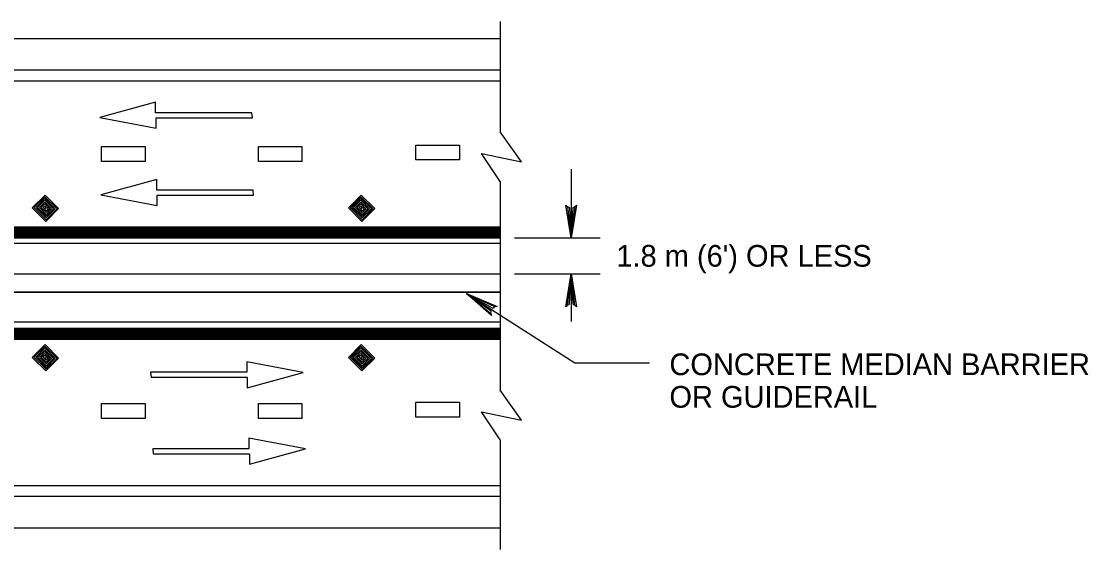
# Model space of a CAD drawing. Extents: x 639362 to 641108, y 298458 to 299646.
# Drawn here: x 639830.9 to 639978.6, y 299371.1 to 299444.2 of the extents above; entities that cross this region are included whole.
import ezdxf

# ---------------------------------------------------------------- set-up
doc = ezdxf.new("R2010")
doc.units = 0
doc.layers.add('2', color=7, linetype='Continuous')

msp = doc.modelspace()

# ---------------------------------------------------------------- linework, layer by layer
at = {"layer": '2'}
for p, q in [((639897.17, 299444.19), (639897.17, 299428.91)), ((639662.67, 299441.83), (639897.17, 299441.83)), ((639662.67, 299437.48), (639897.17, 299437.48)), ((639662.67, 299435.98), (639897.17, 299435.98)), ((639849.5, 299433.01), (639841.78, 299430.89)), ((639849.5, 299431.56), (639849.5, 299433.01)), ((639841.78, 299430.89), (639849.58, 299429.42)), ((639862.83, 299431.56), (639849.5, 299431.56)), ((639849.58, 299429.42), (639849.58, 299430.86)), ((639849.58, 299430.86), (639862.91, 299430.86)), ((639862.91, 299430.89), (639862.83, 299431.56)), ((639862.91, 299430.86), (639862.91, 299430.89)), ((639900.12, 299424.78), (639897.17, 299428.91)), ((639842.04, 299424.83), (639842.04, 299426.9)), ((639842.04, 299426.9), (639848.05, 299426.9)), ((639848.05, 299426.9), (639848.05, 299424.83)), ((639863.74, 299424.83), (639863.74, 299426.9)), ((639863.74, 299426.9), (639869.75, 299426.9)), ((639869.75, 299426.9), (639869.75, 299424.83)), ((639885.51, 299425.02), (639885.51, 299427.08)), ((639885.51, 299427.08), (639891.52, 299427.08)), ((639891.52, 299427.08), (639891.52, 299425.02)), ((639897.17, 299422.04), (639894.6, 299425.91)), ((639894.6, 299425.91), (639900.12, 299424.78)), ((639848.05, 299424.83), (639842.04, 299424.83)), ((639869.75, 299424.83), (639863.74, 299424.83)), ((639891.52, 299425.02), (639885.51, 299425.02)), ((639906.99, 299423.74), (639906.99, 299414.25)), ((639849.65, 299422.3), (639841.93, 299420.18)), ((639849.65, 299420.86), (639849.65, 299422.3)), ((639897.17, 299422.04), (639897.17, 299393.18)), ((639832.45, 299418.4), (639834.21, 299420.17)), ((639832.67, 299418.44), (639834.18, 299419.94)), ((639834.18, 299419.94), (639835.87, 299418.25)), ((639834.21, 299420.17), (639836.09, 299418.29)), ((639841.93, 299420.18), (639849.73, 299418.71)), ((639862.98, 299420.86), (639849.65, 299420.86)), ((639849.73, 299418.71), (639849.73, 299420.15)), ((639849.73, 299420.15), (639863.06, 299420.15)), ((639863.06, 299420.18), (639862.98, 299420.86)), ((639863.06, 299420.15), (639863.06, 299420.18)), ((639876.17, 299418.4), (639877.94, 299420.17)), ((639876.4, 299418.44), (639877.9, 299419.94)), ((639877.9, 299419.94), (639879.6, 299418.25)), ((639877.94, 299420.17), (639879.81, 299418.29)), ((639834.32, 299416.53), (639832.45, 299418.4)), ((639834.36, 299416.75), (639832.67, 299418.44)), ((639832.92, 299418.44), (639834.18, 299419.7)), ((639834.37, 299417), (639832.92, 299418.44)), ((639833.17, 299418.44), (639834.18, 299419.44)), ((639834.37, 299417.25), (639833.17, 299418.44)), ((639833.43, 299418.44), (639834.18, 299419.19)), ((639834.37, 299417.5), (639833.43, 299418.44)), ((639833.68, 299418.44), (639834.18, 299418.94)), ((639834.37, 299417.75), (639833.68, 299418.44)), ((639833.93, 299418.44), (639834.18, 299418.69)), ((639834.37, 299418), (639833.93, 299418.44)), ((639834.17, 299418.44), (639834.36, 299418.25)), ((639834.18, 299419.7), (639835.62, 299418.25)), ((639834.18, 299419.44), (639835.37, 299418.25)), ((639834.18, 299419.19), (639835.12, 299418.25)), ((639834.18, 299418.94), (639834.87, 299418.25)), ((639834.18, 299418.69), (639834.62, 299418.25)), ((639836.09, 299418.29), (639834.32, 299416.53)), ((639878.05, 299416.53), (639876.17, 299418.4)), ((639878.09, 299416.75), (639876.4, 299418.44)), ((639876.65, 299418.44), (639877.9, 299419.7)), ((639878.09, 299417), (639876.65, 299418.44)), ((639876.9, 299418.44), (639877.9, 299419.44)), ((639878.09, 299417.25), (639876.9, 299418.44)), ((639877.15, 299418.44), (639877.9, 299419.19)), ((639878.09, 299417.5), (639877.15, 299418.44)), ((639877.4, 299418.44), (639877.9, 299418.94)), ((639878.09, 299417.75), (639877.4, 299418.44)), ((639877.65, 299418.44), (639877.9, 299418.69)), ((639878.09, 299418), (639877.65, 299418.44)), ((639877.9, 299419.7), (639879.35, 299418.25)), ((639877.9, 299419.44), (639879.1, 299418.25)), ((639877.9, 299419.19), (639878.84, 299418.25)), ((639877.9, 299418.94), (639878.59, 299418.25)), ((639877.9, 299418.69), (639878.34, 299418.25)), ((639877.9, 299418.44), (639878.09, 299418.25)), ((639879.81, 299418.29), (639878.05, 299416.53)), ((639835.87, 299418.25), (639834.36, 299416.75)), ((639835.62, 299418.25), (639834.37, 299417)), ((639835.37, 299418.25), (639834.37, 299417.25)), ((639835.12, 299418.25), (639834.37, 299417.5)), ((639834.87, 299418.25), (639834.37, 299417.75)), ((639834.62, 299418.25), (639834.37, 299418)), ((639879.6, 299418.25), (639878.09, 299416.75)), ((639879.35, 299418.25), (639878.09, 299417)), ((639879.1, 299418.25), (639878.09, 299417.25)), ((639878.84, 299418.25), (639878.09, 299417.5)), ((639878.59, 299418.25), (639878.09, 299417.75)), ((639878.34, 299418.25), (639878.09, 299418)), ((639662.67, 299415.75), (639897.17, 299415.75)), ((639662.67, 299415.6), (639897.17, 299415.6)), ((639662.67, 299415.45), (639897.17, 299415.45)), ((639662.67, 299415.3), (639897.17, 299415.3)), ((639662.67, 299415.15), (639897.17, 299415.15)), ((639662.67, 299415), (639897.17, 299415)), ((639662.67, 299414.85), (639897.17, 299414.85)), ((639662.67, 299414.7), (639897.17, 299414.7)), ((639662.67, 299414.55), (639897.17, 299414.55)), ((639662.67, 299414.4), (639897.17, 299414.4)), ((639662.67, 299414.25), (639897.17, 299414.25)), ((639899.17, 299414.25), (639910.99, 299414.25)), ((639662.67, 299413.5), (639897.17, 299413.5)), ((639662.67, 299409.25), (639897.17, 299409.25)), ((639899.17, 299409.25), (639910.99, 299409.25)), ((639906.99, 299409.25), (639906.99, 299402.7)), ((639662.67, 299406.75), (639897.17, 299406.75)), ((639892.5, 299406.53), (639907.5, 299396.95)), ((639662.67, 299402.65), (639897.17, 299402.65)), ((639662.67, 299401.75), (639897.17, 299401.75)), ((639662.67, 299401.75), (639897.17, 299401.75)), ((639662.67, 299401.75), (639897.17, 299401.75)), ((639662.67, 299401.6), (639897.17, 299401.6)), ((639662.67, 299401.45), (639897.17, 299401.45)), ((639662.67, 299401.3), (639897.17, 299401.3)), ((639662.67, 299401.15), (639897.17, 299401.15)), ((639662.67, 299401), (639897.17, 299401)), ((639662.67, 299400.85), (639897.17, 299400.85)), ((639662.67, 299400.7), (639897.17, 299400.7)), ((639662.67, 299400.55), (639897.17, 299400.55)), ((639662.67, 299400.4), (639897.17, 299400.4)), ((639662.67, 299400.25), (639897.17, 299400.25)), ((639832.45, 299397.72), (639834.21, 299399.49)), ((639832.67, 299397.76), (639834.18, 299399.27)), ((639834.18, 299399.27), (639835.87, 299397.57)), ((639834.21, 299399.49), (639836.09, 299397.62)), ((639876.17, 299397.72), (639877.94, 299399.49)), ((639876.4, 299397.76), (639877.9, 299399.27)), ((639877.9, 299399.27), (639879.6, 299397.57)), ((639877.94, 299399.49), (639879.81, 299397.62)), ((639834.32, 299395.85), (639832.45, 299397.72)), ((639834.36, 299396.07), (639832.67, 299397.76)), ((639832.92, 299397.76), (639834.18, 299399.02)), ((639834.37, 299396.32), (639832.92, 299397.76)), ((639833.17, 299397.76), (639834.18, 299398.77)), ((639834.37, 299396.57), (639833.17, 299397.76)), ((639833.43, 299397.76), (639834.18, 299398.52)), ((639834.37, 299396.82), (639833.43, 299397.76)), ((639833.68, 299397.76), (639834.18, 299398.26)), ((639834.37, 299397.07), (639833.68, 299397.76)), ((639833.93, 299397.76), (639834.18, 299398.02)), ((639834.37, 299397.32), (639833.93, 299397.76)), ((639834.17, 299397.76), (639834.36, 299397.57)), ((639834.18, 299399.02), (639835.62, 299397.58)), ((639834.18, 299398.77), (639835.37, 299397.58)), ((639834.18, 299398.52), (639835.12, 299397.58)), ((639834.18, 299398.26), (639834.87, 299397.58)), ((639834.18, 299398.02), (639834.62, 299397.58)), ((639836.09, 299397.62), (639834.32, 299395.85)), ((639878.05, 299395.85), (639876.17, 299397.72)), ((639878.09, 299396.07), (639876.4, 299397.76)), ((639876.65, 299397.76), (639877.9, 299399.02)), ((639878.09, 299396.32), (639876.65, 299397.76)), ((639876.9, 299397.76), (639877.9, 299398.77)), ((639878.09, 299396.57), (639876.9, 299397.76)), ((639877.15, 299397.76), (639877.9, 299398.52)), ((639878.09, 299396.82), (639877.15, 299397.76)), ((639877.4, 299397.76), (639877.9, 299398.26)), ((639878.09, 299397.07), (639877.4, 299397.76)), ((639877.65, 299397.76), (639877.9, 299398.02)), ((639878.09, 299397.32), (639877.65, 299397.76)), ((639877.9, 299399.02), (639879.35, 299397.58)), ((639877.9, 299398.77), (639879.1, 299397.58)), ((639877.9, 299398.52), (639878.84, 299397.58)), ((639877.9, 299398.26), (639878.59, 299397.58)), ((639877.9, 299398.02), (639878.34, 299397.58)), ((639877.9, 299397.76), (639878.09, 299397.57)), ((639879.81, 299397.62), (639878.05, 299395.85)), ((639835.87, 299397.57), (639834.36, 299396.07)), ((639835.62, 299397.58), (639834.37, 299396.32)), ((639835.37, 299397.58), (639834.37, 299396.57)), ((639835.12, 299397.58), (639834.37, 299396.82)), ((639834.87, 299397.58), (639834.37, 299397.07)), ((639834.62, 299397.58), (639834.37, 299397.32)), ((639869.92, 299395.63), (639862.11, 299397.1)), ((639862.11, 299397.1), (639862.11, 299395.66)), ((639879.35, 299397.58), (639878.09, 299396.32)), ((639879.1, 299397.58), (639878.09, 299396.57)), ((639878.84, 299397.58), (639878.09, 299396.82)), ((639878.59, 299397.58), (639878.09, 299397.07)), ((639878.34, 299397.58), (639878.09, 299397.32)), ((639879.6, 299397.57), (639878.09, 299396.07)), ((639907.5, 299396.95), (639917.81, 299396.95)), ((639848.78, 299395.66), (639848.78, 299395.63)), ((639862.11, 299395.66), (639848.78, 299395.66)), ((639848.78, 299395.63), (639848.87, 299394.96)), ((639848.87, 299394.96), (639862.19, 299394.96)), ((639862.19, 299393.51), (639869.92, 299395.63)), ((639862.19, 299394.96), (639862.19, 299393.51)), ((639900.12, 299389.05), (639897.17, 299393.18)), ((639842.04, 299389.26), (639842.04, 299391.32)), ((639842.04, 299391.32), (639848.05, 299391.32)), ((639848.05, 299391.32), (639848.05, 299389.26)), ((639863.74, 299389.26), (639863.74, 299391.32)), ((639863.74, 299391.32), (639869.75, 299391.32)), ((639869.75, 299391.32), (639869.75, 299389.26)), ((639885.51, 299389.45), (639885.51, 299391.51)), ((639885.51, 299391.51), (639891.52, 299391.51)), ((639891.52, 299391.51), (639891.52, 299389.45)), ((639848.05, 299389.26), (639842.04, 299389.26)), ((639869.75, 299389.26), (639863.74, 299389.26)), ((639891.52, 299389.45), (639885.51, 299389.45)), ((639897.17, 299386.31), (639894.6, 299390.18)), ((639894.6, 299390.18), (639900.12, 299389.05)), ((639870.23, 299385.06), (639862.42, 299386.54)), ((639862.42, 299386.54), (639862.42, 299385.09)), ((639897.17, 299386.31), (639897.17, 299371.13)), ((639849.1, 299385.09), (639849.1, 299385.06)), ((639862.42, 299385.09), (639849.1, 299385.09)), ((639849.1, 299385.06), (639849.18, 299384.39)), ((639849.18, 299384.39), (639862.5, 299384.39)), ((639862.5, 299382.95), (639870.23, 299385.06)), ((639862.5, 299384.39), (639862.5, 299382.95)), ((639662.67, 299380.01), (639897.17, 299380.01)), ((639662.67, 299378.51), (639897.17, 299378.51)), ((639662.67, 299374.16), (639897.17, 299374.16))]:
    msp.add_line(p, q, dxfattribs=at)
for points in [[(639907.53, 299418.57), (639907.23, 299418.41), (639906.99, 299414.25), (639907.53, 299418.57), (639907.73, 299418.79), (639906.99, 299414.25), (639906.79, 299418.4), (639906.48, 299418.55), (639906.99, 299414.25), (639906.27, 299418.79), (639906.48, 299418.55)], [(639906.45, 299404.93), (639906.76, 299405.09), (639906.99, 299409.25), (639906.45, 299404.93), (639906.26, 299404.71), (639906.99, 299409.25), (639907.2, 299405.1), (639907.51, 299404.94), (639906.99, 299409.25), (639907.71, 299404.71), (639907.51, 299404.94)], [(639895.88, 299403.79), (639895.91, 299404.13), (639892.5, 299406.53), (639895.88, 299403.79), (639895.97, 299403.5), (639892.5, 299406.53), (639896.14, 299404.51), (639896.43, 299404.69), (639892.5, 299406.53), (639896.74, 299404.74), (639896.43, 299404.69)]]:
    msp.add_lwpolyline(points, dxfattribs=at)
msp.add_lwpolyline([(639662.67, 299409.25), (639897.17, 299409.25), (639897.17, 299406.75), (639662.67, 299406.75)], close=True, dxfattribs=at)

# ---------------------------------------------------------------- texts
for s, p in [("1.8 m (6') OR LESS", (639913.24, 299410.26)), ('CONCRETE MEDIAN BARRIER', (639920.58, 299395.26)), ('OR GUIDERAIL', (639920.58, 299390.76))]:
    msp.add_text(s, height=3, dxfattribs=at).set_placement(p)

doc.saveas('drawing.dxf')
